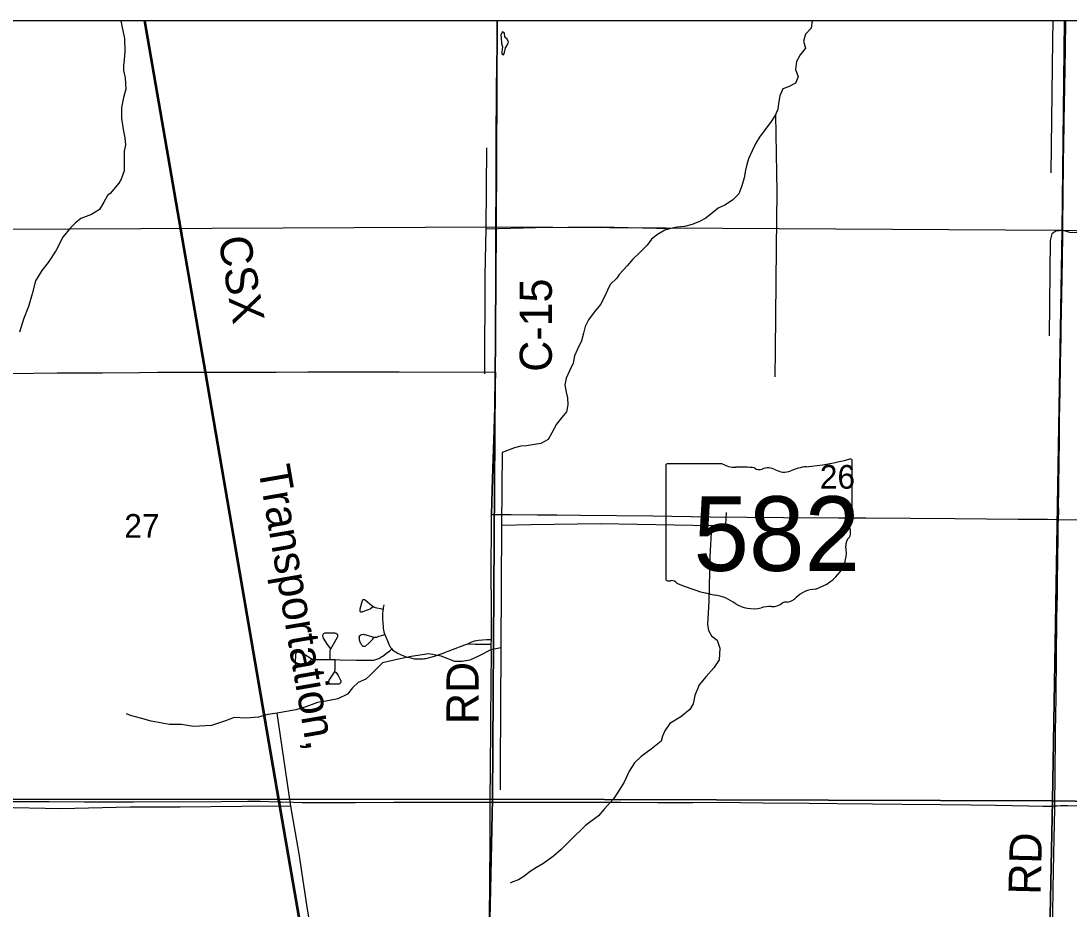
# Model space of a CAD drawing. Extents: x 0 to 34, y 0 to 22.
# Drawn here: x 4.321 to 6.172, y 19.331 to 20.9 of the extents above; entities that cross this region are included whole.
import ezdxf

# ---------------------------------------------------------------- set-up
doc = ezdxf.new("R2010")
doc.units = 0
for name, color, linetype in [('Default', 7, 'Continuous'), ('GM_X_County_Road', 7, 'Continuous'), ('GM_X_County_Road_Text', 7, 'Continuous'), ('GM_X_Minor_Lake', 7, 'Continuous'), ('GM_X_Minor_River', 7, 'Continuous'), ('GM_X_Rail_Line', 7, 'Continuous'), ('GM_X_Rail_Line_Text', 7, 'Continuous'), ('GM_X_Section', 7, 'Continuous'), ('GM_X_Section_Text', 7, 'Continuous'), ('GM_X_State_Location', 7, 'Continuous'), ('GM_X_State_Route', 7, 'Continuous'), ('GM_X_State_Shield', 7, 'Continuous'), ('GM_X_Township_Road', 7, 'Continuous'), ('GM_X_Township_Road_Text', 7, 'Continuous'), ('SH_Cut_Line', 7, 'Continuous')]:
    doc.layers.add(name, color=color, linetype=linetype)

msp = doc.modelspace()

# ---------------------------------------------------------------- linework, layer by layer
at = {"layer": 'Default'}
msp.add_lwpolyline([(7.1734, 20.9), (3.1549, 20.9)], dxfattribs=at)
for points in [[(5.1619, 20.9), (4.1599, 20.9), (4.1565, 20.5312), (5.1605, 20.536)], [(6.1646, 20.9), (5.1619, 20.9), (5.1605, 20.536), (6.1602, 20.5302)], [(7.1717, 20.9), (6.1646, 20.9), (6.1602, 20.5302), (7.1654, 20.5062)]]:
    msp.add_lwpolyline(points, close=True, dxfattribs=at)
at = {"layer": 'GM_X_County_Road'}
for points in [[(5.1594, 20.2793), (5.1592, 20.3183), (5.1596, 20.3512), (5.1595, 20.3674), (5.1598, 20.4066), (5.1601, 20.4557), (5.1601, 20.5297), (5.1604, 20.613), (5.1603, 20.6441), (5.1605, 20.6646), (5.1606, 20.6807), (5.1606, 20.7124), (5.1609, 20.7529), (5.1612, 20.7845), (5.1622, 20.8458), (5.1622, 20.8713), (5.1621, 20.9)], [(5.152, 20.0279), (5.1541, 20.0915), (5.1547, 20.1089), (5.1562, 20.1595), (5.1572, 20.1973), (5.1578, 20.2189), (5.1583, 20.235), (5.1594, 20.2793)], [(5.1518, 19.7986), (5.1519, 19.8069), (5.152, 19.819), (5.152, 19.8458), (5.152, 19.8818), (5.1518, 19.9073), (5.1518, 19.9216), (5.1517, 19.949), (5.1519, 19.9898), (5.152, 20.0279)], [(5.15, 19.5196), (5.15, 19.5276), (5.1501, 19.5728), (5.151, 19.6586), (5.1516, 19.7363), (5.1519, 19.7774), (5.1518, 19.7979), (5.1518, 19.7986)], [(5.1419, 19.0116), (5.1428, 19.0494), (5.1441, 19.1004), (5.1444, 19.1253), (5.145, 19.1638), (5.1461, 19.2054), (5.1473, 19.2682), (5.1484, 19.3248), (5.149, 19.3671), (5.1492, 19.3882), (5.1498, 19.4392), (5.1499, 19.502), (5.15, 19.5196)]]:
    msp.add_lwpolyline(points, dxfattribs=at)
at = {"layer": 'GM_X_Minor_Lake'}
msp.add_line((5.1699, 20.8605), (5.1713, 20.854), dxfattribs=at)
msp.add_lwpolyline([(5.1713, 20.854), (5.1707, 20.845), (5.1706, 20.8419), (5.1732, 20.8403), (5.1752, 20.8441), (5.1769, 20.8524), (5.1793, 20.8557), (5.1821, 20.8625), (5.1796, 20.8675), (5.1759, 20.8714), (5.1753, 20.8782), (5.1716, 20.881), (5.1688, 20.8757), (5.169, 20.8704), (5.1699, 20.8605)], dxfattribs=at)
at = {"layer": 'GM_X_Minor_River'}
for points in [[(4.4972, 20.9), (4.4996, 20.8881), (4.504, 20.8691), (4.5046, 20.8459), (4.5031, 20.8311), (4.5021, 20.8213), (4.5022, 20.8122), (4.5049, 20.7996), (4.5063, 20.7794), (4.5018, 20.7647), (4.4983, 20.747), (4.4982, 20.728), (4.5015, 20.7082), (4.5042, 20.6937), (4.5058, 20.6808), (4.5032, 20.6698), (4.5032, 20.6539), (4.5031, 20.6349), (4.4978, 20.6202), (4.4939, 20.6131), (4.4787, 20.5953), (4.4736, 20.5916), (4.4673, 20.5796), (4.4594, 20.5665), (4.4452, 20.5581), (4.4264, 20.5506), (4.4168, 20.5425), (4.4086, 20.5344), (4.3949, 20.5176), (4.3822, 20.494), (4.3692, 20.4731), (4.3575, 20.4589), (4.3464, 20.4406), (4.3406, 20.418), (4.3343, 20.3954), (4.3254, 20.3728), (4.3181, 20.3498)], [(5.7185, 20.9), (5.7167, 20.8875), (5.7069, 20.8767), (5.7032, 20.8643), (5.7067, 20.8517), (5.6977, 20.8398), (5.691, 20.8282), (5.6895, 20.8142), (5.6941, 20.8012), (5.6893, 20.7899), (5.6766, 20.7837), (5.6671, 20.7802), (5.6618, 20.7674), (5.6592, 20.7542), (5.6578, 20.7443), (5.6538, 20.7338), (5.6451, 20.7204), (5.6357, 20.7081), (5.6256, 20.6947), (5.6189, 20.6842), (5.6125, 20.6707), (5.6064, 20.6564), (5.6035, 20.6462), (5.601, 20.636), (5.5984, 20.6225), (5.5943, 20.6085), (5.5894, 20.5946), (5.5781, 20.5835), (5.5646, 20.5747), (5.5528, 20.5693), (5.5431, 20.5616), (5.5311, 20.5512), (5.5196, 20.5454), (5.5066, 20.5404), (5.4929, 20.537), (5.48, 20.5354), (5.4686, 20.5334), (5.4586, 20.5302), (5.4456, 20.5225), (5.4351, 20.5141), (5.4269, 20.5036), (5.4137, 20.4903), (5.4017, 20.4792), (5.3916, 20.4673), (5.3778, 20.4519), (5.3736, 20.4457), (5.3619, 20.4342), (5.3568, 20.4241), (5.3516, 20.4125), (5.3448, 20.3986), (5.3338, 20.3852), (5.3237, 20.3718), (5.3177, 20.3602), (5.3147, 20.3481)], [(6.1409, 20.6313), (6.1437, 20.8654), (6.1442, 20.9)], [(5.6538, 20.7338), (5.6561, 20.5975), (5.6552, 20.4993), (5.6533, 20.3179), (5.6529, 20.2712)], [(5.1403, 20.2761), (5.1408, 20.4499), (5.1425, 20.5325), (5.1441, 20.676)], [(5.1425, 20.5325), (5.23, 20.535), (5.3444, 20.536), (5.4686, 20.5334)], [(6.4085, 20.5208), (6.3, 20.5246), (6.1739, 20.5261), (6.1619, 20.5299), (6.1493, 20.5283), (6.142, 20.5235), (6.1391, 20.5122), (6.1372, 20.3437)], [(5.3147, 20.3481), (5.311, 20.3345), (5.3038, 20.3199), (5.299, 20.3083), (5.2964, 20.295), (5.2908, 20.2827), (5.284, 20.2688), (5.2818, 20.2567), (5.2841, 20.2437), (5.2862, 20.2338), (5.287, 20.2216), (5.2844, 20.2092), (5.2758, 20.1984), (5.2672, 20.1872), (5.2589, 20.1722), (5.2525, 20.1602), (5.2395, 20.153), (5.2281, 20.1517), (5.214, 20.1494), (5.2041, 20.1485), (5.1927, 20.1458), (5.1709, 20.1375)], [(5.1709, 20.1375), (5.17, 20.0085), (5.1688, 19.7919), (5.1677, 19.5813), (5.1675, 19.5415)], [(5.5667, 20.0312), (5.5654, 20.01), (5.5411, 20.0075), (5.3446, 20.0111), (5.222, 20.0093), (5.17, 20.0085)], [(5.5411, 20.0075), (5.5378, 19.9526), (5.5359, 19.8741), (5.5337, 19.8339), (5.5357, 19.8225), (5.5408, 19.8136), (5.5508, 19.8058), (5.5554, 19.7916), (5.5545, 19.7712), (5.5451, 19.7566), (5.5315, 19.7417), (5.519, 19.7265), (5.5113, 19.7081), (5.5087, 19.6933), (5.5024, 19.6832), (5.4869, 19.6703), (5.4673, 19.6587), (5.4586, 19.6456), (5.4542, 19.6358), (5.4521, 19.6272), (5.434, 19.6128), (5.4166, 19.5999), (5.405, 19.5888), (5.3955, 19.5743), (5.3863, 19.5548), (5.3745, 19.5357), (5.3678, 19.5252), (5.351, 19.507), (5.3413, 19.4955), (5.3181, 19.4782), (5.2925, 19.453), (5.275, 19.4356), (5.2619, 19.4242), (5.243, 19.4106), (5.2318, 19.404), (5.2203, 19.3971), (5.2091, 19.3879), (5.1999, 19.382), (5.1896, 19.3785), (5.1849, 19.376)], [(5.1688, 19.7919), (5.1509, 19.7885), (5.1306, 19.778), (5.1141, 19.7701), (5.1, 19.7681), (5.0871, 19.7681), (5.0635, 19.7777), (5.0413, 19.7813), (5.0105, 19.7767), (4.988, 19.7724), (4.9598, 19.7658), (4.9377, 19.7436), (4.93, 19.7366), (4.9166, 19.7308), (4.9065, 19.7216), (4.8979, 19.7104), (4.8806, 19.7021), (4.8631, 19.6983), (4.8449, 19.6957), (4.8242, 19.6879), (4.8063, 19.6826), (4.7736, 19.6766), (4.7569, 19.6744), (4.7405, 19.6698), (4.7181, 19.6677), (4.6973, 19.669), (4.682, 19.6633), (4.6575, 19.6551), (4.6257, 19.6529), (4.6046, 19.6564), (4.583, 19.6569), (4.5509, 19.6626), (4.5321, 19.668), (4.5144, 19.6726), (4.5073, 19.6758)], [(4.9742, 18.4232), (4.9512, 18.5653), (4.9187, 18.7654), (4.8806, 19.0012), (4.851, 19.1822), (4.8258, 19.338), (4.8125, 19.4279), (4.7979, 19.5125), (4.7736, 19.6766)], [(4.7979, 19.5125), (4.7112, 19.5115), (4.6024, 19.5107), (4.5135, 19.5106), (4.3911, 19.5079), (4.2794, 19.5098), (4.1499, 19.5095), (4.0688, 19.5085), (4.059, 19.511), (4.0491, 19.5089), (4.0364, 19.4994), (4.0167, 19.4854), (3.9956, 19.4742), (3.9711, 19.4607), (3.9184, 19.4298), (3.8927, 19.416), (3.8782, 19.4114), (3.8645, 19.4094), (3.814, 19.4035)]]:
    msp.add_lwpolyline(points, dxfattribs=at)
at = {"layer": 'GM_X_Rail_Line'}
for points in [[(5.1845, 16.9583), (5.1759, 17.0275), (5.1512, 17.2319), (5.1278, 17.4186), (5.1173, 17.5021), (5.1014, 17.6375), (5.0581, 17.8798), (4.9514, 18.5044), (4.7757, 19.5202), (4.6462, 20.2762), (4.5385, 20.9)], [(5.533, 14.1), (5.4414, 14.8452), (5.2368, 16.5291), (5.1973, 16.873), (5.1794, 17.0253), (5.1537, 17.2322), (5.1303, 17.4189), (5.1198, 17.5024), (5.1038, 17.6379), (5.0605, 17.8802), (4.9539, 18.5048), (4.7781, 19.5207), (4.6486, 20.2766), (4.541, 20.9)]]:
    msp.add_lwpolyline(points, dxfattribs=at)
at = {"layer": 'GM_X_Section'}
for points in [[(5.1605, 20.536), (5.1538, 19.525), (4.1507, 19.5243), (4.1565, 20.5312)], [(6.1602, 20.5302), (6.1433, 19.5215), (5.1538, 19.525), (5.1605, 20.536)], [(7.1654, 20.5062), (7.1646, 20.4494), (7.146, 19.507), (6.1433, 19.5215), (6.1602, 20.5302)], [(5.1538, 19.525), (5.1313, 18.516), (5.1123, 18.5161), (4.1339, 18.5191), (4.1507, 19.5243)], [(6.1433, 19.5215), (6.1226, 18.5095), (6.0923, 18.5098), (5.1313, 18.516), (5.1538, 19.525)], [(7.146, 19.507), (7.145, 19.4532), (7.1287, 18.4994), (6.1226, 18.5095), (6.1433, 19.5215)]]:
    msp.add_lwpolyline(points, close=True, dxfattribs=at)
at = {"layer": 'GM_X_State_Route'}
for points in [[(4.151, 20.277), (4.1544, 20.2769), (4.1743, 20.2767), (4.3008, 20.2769), (4.3849, 20.2779), (4.4284, 20.2784), (4.4645, 20.2784), (4.5303, 20.279), (4.5626, 20.2794), (4.6054, 20.2791), (4.6421, 20.2792), (4.6629, 20.2793), (4.7213, 20.2795), (4.7716, 20.2796), (4.8276, 20.2797), (4.8723, 20.2799), (4.9892, 20.2798), (5.1594, 20.2793)], [(5.1594, 20.2793), (5.1583, 20.235), (5.1578, 20.2189), (5.1572, 20.1973), (5.1562, 20.1595), (5.1547, 20.1089), (5.1541, 20.0915), (5.152, 20.0279)], [(5.152, 20.0279), (5.1869, 20.0278), (5.2336, 20.0274), (5.2678, 20.0272), (5.3094, 20.0266), (5.4374, 20.0252), (5.5382, 20.0237), (5.6681, 20.0223), (5.765, 20.0217), (5.8135, 20.0217), (5.8925, 20.0215), (5.9709, 20.0206), (6.0827, 20.0195), (6.1343, 20.0193), (6.1537, 20.0192), (6.2312, 20.0182)]]:
    msp.add_lwpolyline(points, dxfattribs=at)
at = {"layer": 'GM_X_State_Shield'}
for p, q in [((5.46, 20.1141), (5.46, 19.914)), ((5.5598, 20.1175), (5.4633, 20.1175)), ((5.7896, 20.0178), (5.7896, 20.1225)), ((5.7896, 20.0178), (5.7896, 20.0178))]:
    msp.add_line(p, q, dxfattribs=at)
for centre, major_axis, start_param, end_param in [((5.4638, 20.1145), (0.00382, 0), 1.712693, 3.28349), ((5.5828, 20.1408), (0.037, 0), 4.042523, 4.731795), ((5.595, 20.0052), (0.133, 0), 1.404758, 1.657858), ((5.6252, 20.1155), (0.0107, 0), 3.836095, 5.185415), ((5.6409, 20.0924), (0.0222, 0), 0.950623, 2.079405), ((5.7168, 20.0564), (0.0703, 0), 1.699011, 2.107814), ((5.6722, 20.3904), (0.3495, 0), 4.814394, 5.042369), ((5.7859, 20.1229), (0.00367, 0), 6.141152, 7.989035), ((5.6696, 20.1241), (0.0267, 0), 4.081561, 5.145723), ((5.7857, 20.0174), (0.00393, 0), 5.05454, 6.418171), ((5.7887, 20.0101), (0.00568, 0), 1.883978, 3.671073), ((5.7526, 19.9969), (0.0341, 0), 5.934695, 6.695948), ((5.8027, 19.974), (0.0248, 0), 2.387724, 3.262537), ((5.6918, 19.9607), (0.0874, 0), 5.101752, 6.440018), ((5.4638, 19.9135), (0.00385, 0), 3.00124, 4.508301), ((5.4644, 19.934), (0.0294, 0), 4.665946, 4.897461), ((5.4704, 19.9024), (0.0106, 0), 0.519207, 1.627899), ((5.6042, 20.0822), (0.2524, 0), 4.195997, 4.488961), ((5.7286, 19.8578), (0.0479, 0), 1.647645, 2.488434), ((5.529, 19.8241), (0.079, 0), 0.823519, 1.323587), ((5.6144, 19.9014), (0.0501, 0), 4.026481, 4.996735), ((5.647, 19.8864), (0.0267, 0), 4.691044, 5.507374), ((5.6712, 19.8671), (0.00752, 0), 1.147584, 2.315152), ((5.668, 19.8946), (0.0282, 0), 4.937069, 5.64225), ((5.6434, 19.8322), (0.0412, 0), 1.495662, 1.94098)]:
    msp.add_ellipse(centre, major_axis=major_axis, ratio=0.8, start_param=start_param, end_param=end_param, dxfattribs=at)
at = {"layer": 'GM_X_Township_Road'}
msp.add_line((4.8673, 19.7714), (4.8758, 19.7713), dxfattribs=at)
for points in [[(6.1537, 20.0192), (6.1542, 20.0345), (6.1541, 20.0445), (6.1542, 20.0709), (6.1544, 20.0799), (6.1545, 20.0869), (6.1548, 20.1107), (6.1554, 20.1684), (6.1556, 20.1819), (6.1559, 20.1969), (6.157, 20.245), (6.157, 20.2616), (6.1572, 20.2748), (6.1575, 20.2951), (6.1579, 20.3163), (6.1587, 20.3435), (6.1588, 20.3595), (6.1591, 20.3849), (6.1596, 20.4179), (6.1602, 20.444), (6.1607, 20.4813), (6.1613, 20.5205), (6.1623, 20.61), (6.1625, 20.6299), (6.1628, 20.6473), (6.1629, 20.6572), (6.1631, 20.6746), (6.164, 20.7249), (6.1644, 20.7522), (6.1654, 20.815), (6.166, 20.8529), (6.1666, 20.8983), (6.1666, 20.9)], [(6.1472, 19.5128), (6.1477, 19.5681), (6.148, 19.5883), (6.1487, 19.6194), (6.1487, 19.6411), (6.1491, 19.6753), (6.1495, 19.7017), (6.15, 19.7266), (6.1503, 19.7561), (6.1506, 19.7981), (6.1507, 19.8183), (6.151, 19.8337), (6.1511, 19.8495), (6.1514, 19.863), (6.1518, 19.8878), (6.1521, 19.9035), (6.1519, 19.9158), (6.1525, 19.9411), (6.1529, 19.9597), (6.1532, 19.9785), (6.1534, 19.9938), (6.1532, 20.01), (6.1537, 20.0192)], [(4.9433, 19.8646), (4.9386, 19.8613), (4.937, 19.8604), (4.9344, 19.8593), (4.9242, 19.8555), (4.9229, 19.8553), (4.9222, 19.8552), (4.9215, 19.8553), (4.9207, 19.8557), (4.9202, 19.8564), (4.9199, 19.8573), (4.9199, 19.8584), (4.9204, 19.8613), (4.9243, 19.8758), (4.9245, 19.8765), (4.9252, 19.8774), (4.9257, 19.8777), (4.9269, 19.8778), (4.9276, 19.8777), (4.9286, 19.8772), (4.9294, 19.8766), (4.9409, 19.8669), (4.9423, 19.8658), (4.944, 19.8648), (4.9454, 19.864), (4.9469, 19.8635), (4.9493, 19.863), (4.9559, 19.8616), (4.9606, 19.8605)], [(4.9622, 19.8679), (4.9615, 19.8655), (4.961, 19.863), (4.9606, 19.8605)], [(4.9606, 19.8605), (4.9604, 19.8586), (4.9598, 19.8518), (4.9596, 19.8488), (4.9596, 19.8459), (4.9597, 19.8415), (4.9599, 19.8384), (4.9602, 19.8343), (4.9606, 19.8306), (4.961, 19.8268), (4.9616, 19.8234), (4.9621, 19.8203), (4.9632, 19.8171), (4.9637, 19.8159)], [(4.8673, 19.7714), (4.8671, 19.7852), (4.8672, 19.7867), (4.8674, 19.7878), (4.8679, 19.7891), (4.8684, 19.7905), (4.8802, 19.8111), (4.8805, 19.812), (4.8807, 19.8127), (4.8808, 19.8137), (4.8808, 19.8143), (4.8806, 19.815), (4.8802, 19.8156), (4.8797, 19.816), (4.8792, 19.8165), (4.8785, 19.817), (4.8776, 19.8174), (4.8766, 19.8177), (4.8755, 19.818), (4.8743, 19.8182), (4.861, 19.8182), (4.8581, 19.8179), (4.8573, 19.8178), (4.8563, 19.8175), (4.8555, 19.8171), (4.8546, 19.8162), (4.854, 19.815), (4.8538, 19.8142), (4.8537, 19.8135), (4.8538, 19.8127), (4.854, 19.8118), (4.8545, 19.8105), (4.855, 19.8094), (4.8616, 19.7983), (4.8678, 19.7901)], [(4.9441, 19.8108), (4.9416, 19.8069), (4.9407, 19.8056), (4.9398, 19.8044), (4.9363, 19.8012), (4.9293, 19.7953), (4.9284, 19.7947), (4.9277, 19.7944), (4.927, 19.7943), (4.9263, 19.7943), (4.9256, 19.7945), (4.9249, 19.7948), (4.9243, 19.7953), (4.9236, 19.7962), (4.9228, 19.7973), (4.922, 19.7985), (4.9211, 19.8004), (4.9203, 19.8023), (4.9196, 19.804), (4.9191, 19.806), (4.9189, 19.8076), (4.9188, 19.8089), (4.9186, 19.8102), (4.9187, 19.8111), (4.9189, 19.8122), (4.9191, 19.8131), (4.9195, 19.8137), (4.9199, 19.8142), (4.9205, 19.8147), (4.9215, 19.8153), (4.9226, 19.8156), (4.9241, 19.816), (4.9258, 19.8161), (4.9271, 19.816), (4.9285, 19.8158), (4.9443, 19.8112), (4.9455, 19.811), (4.9467, 19.8109), (4.9481, 19.811), (4.9493, 19.8112), (4.9531, 19.8125), (4.9581, 19.8141), (4.9637, 19.8159)], [(4.9637, 19.8159), (4.9653, 19.8116), (4.9682, 19.8047), (4.9722, 19.7957), (4.973, 19.7945), (4.9739, 19.793), (4.9749, 19.7916), (4.9761, 19.7901)], [(4.9761, 19.7901), (4.9774, 19.7889), (4.9795, 19.7871), (4.9815, 19.7857), (4.9838, 19.7843), (4.9861, 19.7829), (4.9892, 19.7813), (4.9923, 19.7799), (4.9957, 19.7784), (4.9985, 19.7774), (5.0013, 19.7764), (5.0039, 19.7757), (5.0069, 19.7748), (5.0096, 19.7742), (5.0115, 19.7737), (5.0135, 19.7733), (5.0159, 19.773), (5.0184, 19.7728), (5.021, 19.7727), (5.0247, 19.7726), (5.0281, 19.7727), (5.0312, 19.7729), (5.0336, 19.7731), (5.0359, 19.7735), (5.0384, 19.7739), (5.0406, 19.7744), (5.0448, 19.7754), (5.0514, 19.7775), (5.0649, 19.7823), (5.0834, 19.7895), (5.1051, 19.7974), (5.1102, 19.7992)], [(5.1102, 19.7992), (5.1173, 19.8026), (5.1195, 19.8036), (5.1224, 19.8044), (5.1257, 19.8052), (5.1291, 19.8057), (5.1432, 19.8068), (5.1519, 19.8069)], [(5.1102, 19.7992), (5.1231, 19.7985), (5.1466, 19.7986), (5.1518, 19.7986)], [(4.8342, 19.7722), (4.8318, 19.769), (4.8308, 19.768), (4.8298, 19.7674), (4.829, 19.7669), (4.8207, 19.7623), (4.8137, 19.759), (4.8127, 19.7588), (4.8116, 19.7586), (4.8106, 19.7586), (4.8096, 19.7588), (4.8089, 19.7591), (4.8081, 19.7595), (4.8074, 19.76), (4.8069, 19.7606), (4.8065, 19.7612), (4.8063, 19.762), (4.806, 19.7632), (4.8059, 19.7669), (4.8064, 19.7792), (4.8066, 19.7809), (4.8069, 19.7819), (4.8072, 19.7827), (4.8079, 19.7835), (4.8085, 19.7841), (4.8093, 19.7846), (4.8101, 19.785), (4.811, 19.7851), (4.8121, 19.7852), (4.8133, 19.7851), (4.8144, 19.7849), (4.8154, 19.7845), (4.8223, 19.7805), (4.8336, 19.7731), (4.8346, 19.7725), (4.8356, 19.7721), (4.8366, 19.7719), (4.838, 19.7717), (4.8673, 19.7714)], [(4.8758, 19.7713), (4.884, 19.7711), (4.9138, 19.7706), (4.9411, 19.7704), (4.9436, 19.7706), (4.9459, 19.7709), (4.9478, 19.7713), (4.9498, 19.772), (4.9512, 19.7726), (4.953, 19.7734), (4.9547, 19.7743), (4.9567, 19.7754), (4.96, 19.7776), (4.9666, 19.7825), (4.9724, 19.7871), (4.9761, 19.7901)], [(4.8754, 19.7506), (4.8777, 19.7485), (4.8789, 19.747), (4.8813, 19.7434), (4.8833, 19.7396), (4.8849, 19.7364), (4.8854, 19.7353), (4.8857, 19.7342), (4.8859, 19.733), (4.8858, 19.7322), (4.8857, 19.7314), (4.8854, 19.7308), (4.8851, 19.7302), (4.8842, 19.7291), (4.8836, 19.7287), (4.8828, 19.7284), (4.8819, 19.7281), (4.8805, 19.7279), (4.869, 19.7277), (4.868, 19.7278), (4.8673, 19.7281), (4.8664, 19.7285), (4.8657, 19.7291), (4.8653, 19.7296), (4.865, 19.7303), (4.8648, 19.7312), (4.8648, 19.7321), (4.865, 19.7331), (4.8652, 19.734), (4.8656, 19.7348), (4.8745, 19.7494), (4.8751, 19.751), (4.8756, 19.7524), (4.8759, 19.7539), (4.8761, 19.7554), (4.876, 19.7652), (4.8758, 19.7713)], [(4.1428, 19.5207), (4.1683, 19.5208), (4.2461, 19.5209), (4.3704, 19.5205), (4.4326, 19.5201), (4.5196, 19.5199), (4.675, 19.5208), (4.7216, 19.5212), (4.7434, 19.521), (4.759, 19.5207), (4.7745, 19.5201), (4.7807, 19.5198), (4.8024, 19.5192), (4.8179, 19.5189), (4.8676, 19.5186), (4.9111, 19.5187), (4.9795, 19.5192), (5.051, 19.5194), (5.0914, 19.5194), (5.1318, 19.5196), (5.15, 19.5196)], [(5.15, 19.5196), (5.166, 19.5195), (5.2033, 19.5196), (5.2375, 19.5195), (5.3308, 19.5196), (5.3805, 19.5196), (5.4458, 19.5191), (5.5079, 19.5189), (5.5577, 19.5192), (5.5919, 19.5189), (5.6323, 19.5184), (5.7131, 19.5176), (5.7628, 19.5169), (5.825, 19.5164), (5.8778, 19.516), (5.9462, 19.5152), (5.999, 19.5147), (6.0425, 19.5141), (6.1016, 19.5129), (6.1264, 19.5124), (6.1419, 19.5125), (6.1472, 19.5128)], [(6.1382, 19.0071), (6.1384, 19.024), (6.139, 19.0597), (6.1398, 19.1001), (6.1412, 19.1686), (6.1423, 19.2043), (6.143, 19.2587), (6.1435, 19.2851), (6.1437, 19.296), (6.1438, 19.3085), (6.1441, 19.3364), (6.1443, 19.3504), (6.1445, 19.366), (6.1451, 19.3971), (6.1457, 19.4282), (6.1462, 19.4546), (6.1471, 19.5074), (6.1472, 19.5128)], [(6.1472, 19.5128), (6.1512, 19.5131), (6.1574, 19.5133), (6.1699, 19.5134), (6.1979, 19.5128), (6.2414, 19.5116), (6.2849, 19.5109), (6.3408, 19.5102), (6.3968, 19.5096), (6.4745, 19.5085), (6.689, 19.5064), (6.7418, 19.5056), (6.748, 19.5055), (6.8102, 19.5044), (6.8506, 19.5037), (6.8941, 19.5032), (6.9562, 19.5023), (7.0619, 19.5005), (7.1178, 19.4997), (7.1334, 19.4995), (7.1427, 19.4992), (7.1504, 19.4989)]]:
    msp.add_lwpolyline(points, dxfattribs=at)
at = {"layer": 'SH_Cut_Line'}
msp.add_lwpolyline([(7.1734, 20.9), (2.1, 20.9), (2.1, 14.1)], dxfattribs=at)

# ---------------------------------------------------------------- texts
at = {"layer": 'GM_X_County_Road_Text'}
for s, p in [('C-15', (5.2588, 20.28)), ('RD', (5.1294, 19.6575))]:
    msp.add_text(s, height=0.05682, rotation=90, dxfattribs=at).set_placement(p)
at = {"layer": 'GM_X_Rail_Line_Text'}
for s, height, rotation, p in [('CSX', 0.05663, 279.8998, (4.6692, 20.5155)), ('Transportation,', 0.056629, 279.7939, (4.7396, 20.1104))]:
    msp.add_text(s, height=height, rotation=rotation, dxfattribs=at).set_placement(p)
at = {"layer": 'GM_X_Section_Text'}
for s, p in [('26', (5.7322, 20.0734)), ('27', (4.5034, 19.9867))]:
    msp.add_text(s, height=0.04186, rotation=0, dxfattribs=at).set_placement(p)
at = {"layer": 'GM_X_State_Location'}
for s in ['s', 'r']:
    msp.add_text(s, height=0.000189, dxfattribs=at).set_placement((5.6211, 20.0007))
msp.add_text('582', height=0.000189, rotation=0, dxfattribs=at).set_placement((5.5542, 19.9869))
at = {"layer": 'GM_X_State_Shield'}
msp.add_text('582', height=0.13184, dxfattribs=at).set_placement((5.509, 19.9281))
at = {"layer": 'GM_X_Township_Road_Text'}
msp.add_text('RD', height=0.05682, rotation=88.5292, dxfattribs=at).set_placement((6.1221, 19.3554))

doc.saveas('drawing.dxf')
